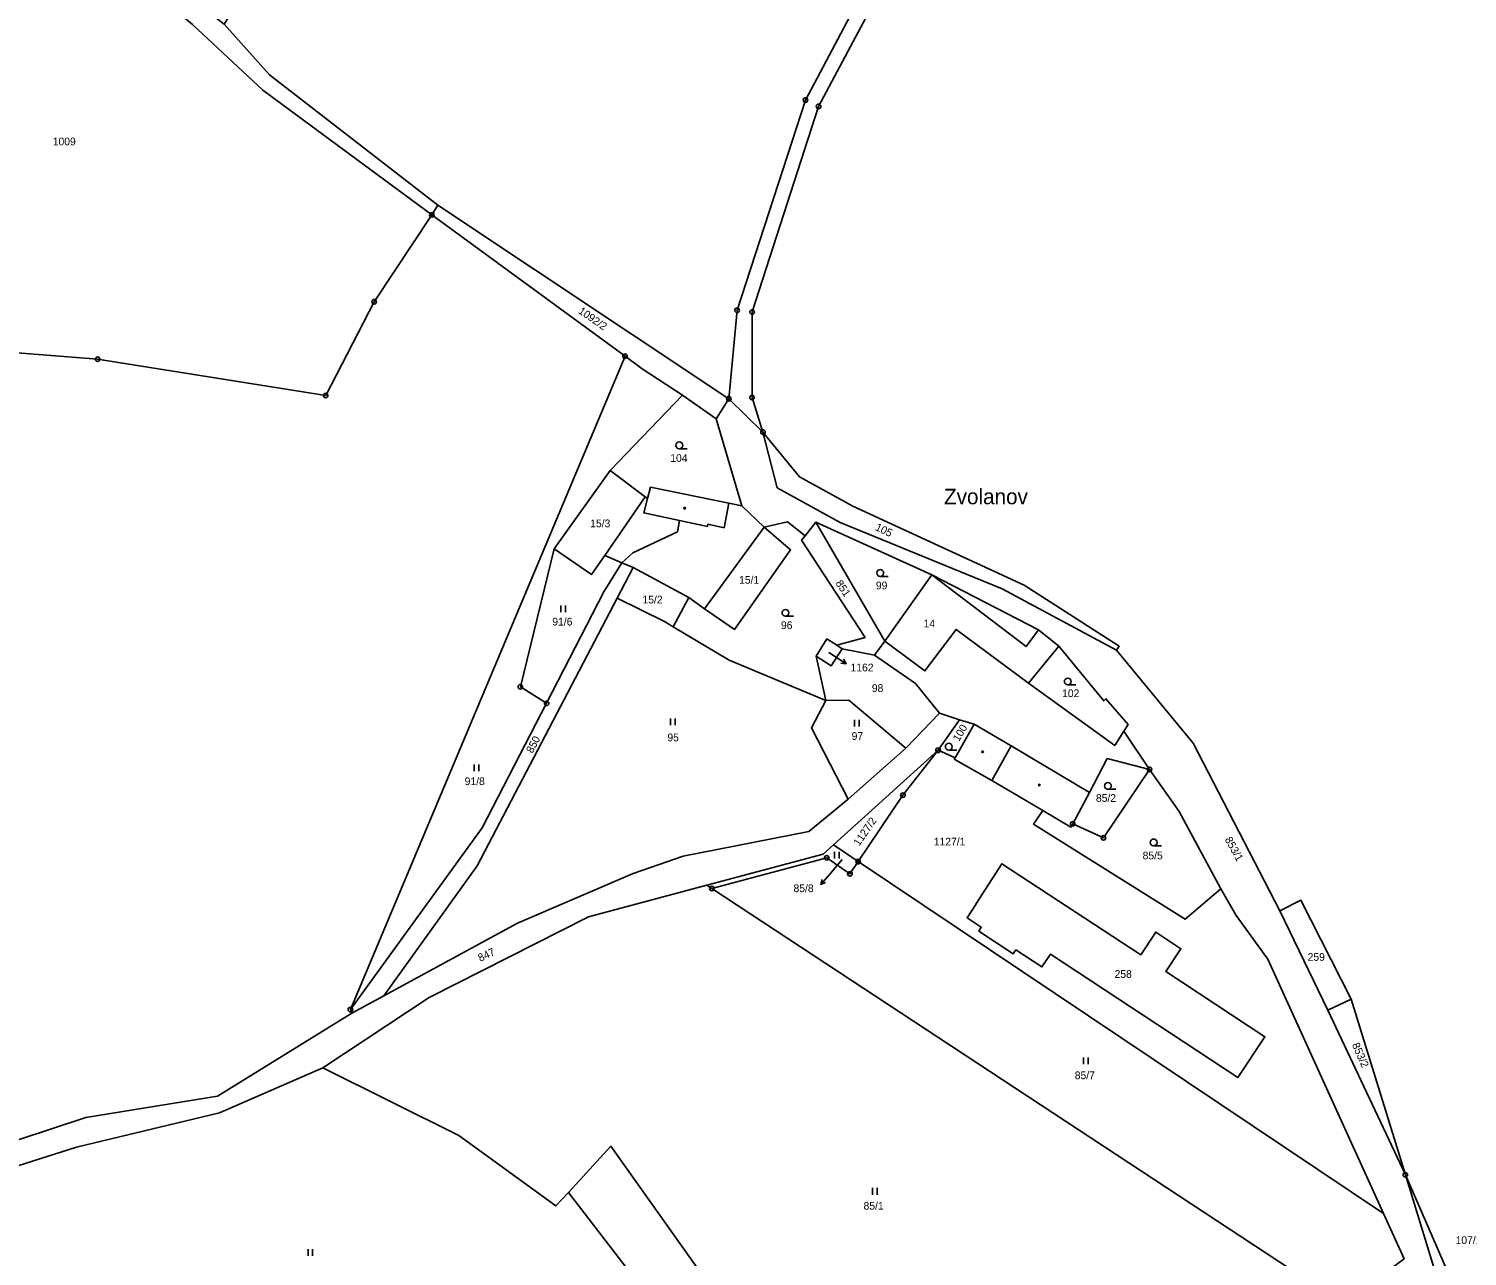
# Model space of a CAD drawing. Extents: x -654083 to -650132, y -1099819 to -1096699.
# Drawn here: x -652774.8 to -652458.4, y -1097734.5 to -1097464.5 of the extents above; entities that cross this region are included whole.
import ezdxf

# ---------------------------------------------------------------- set-up
doc = ezdxf.new("R2010")
doc.units = 0
for name, color, linetype in [('Geodetické body', 7, 'Continuous'), ('Hranice - vnitř_ kresba', 7, 'Continuous'), ('Obvody jako plochy', 7, 'Continuous'), ('Parcelní čísla', 7, 'Continuous'), ('Prvky pro prodl_ par_ č_', 7, 'Continuous'), ('Značky kultur', 7, 'Continuous'), ('Značky na budově ne v SPI', 7, 'Continuous')]:
    doc.layers.add(name, color=color, linetype=linetype)

msp = doc.modelspace()

# ---------------------------------------------------------------- linework, layer by layer
at = {"layer": 'Geodetické body'}
for centre, radius in [((-652603.96, -1097480.16), 0.5), ((-652603.96, -1097480.16), 0.001), ((-652601.09, -1097481.55), 0.5), ((-652601.09, -1097481.55), 0.001), ((-652686.17, -1097505.42), 0.5), ((-652686.17, -1097505.42), 0.001), ((-652698.86, -1097524.53), 0.5), ((-652698.86, -1097524.53), 0.001), ((-652619.02, -1097526.4), 0.5), ((-652619.02, -1097526.4), 0.001), ((-652615.72, -1097526.78), 0.5), ((-652615.72, -1097526.78), 0.001), ((-652759.69, -1097537.16), 0.5), ((-652759.69, -1097537.16), 0.001), ((-652643.67, -1097536.5), 0.5), ((-652643.67, -1097536.5), 0.001), ((-652709.52, -1097545.14), 0.5), ((-652709.52, -1097545.14), 0.001), ((-652620.84, -1097545.87), 0.5), ((-652620.84, -1097545.87), 0.001), ((-652615.73, -1097545.59), 0.5), ((-652615.73, -1097545.59), 0.001), ((-652613.33, -1097553.2), 0.5), ((-652613.33, -1097553.2), 0.001), ((-652666.7, -1097609.23), 0.5), ((-652666.7, -1097609.23), 0.001), ((-652660.92, -1097612.87), 0.5), ((-652660.92, -1097612.87), 0.001), ((-652574.81, -1097623.21), 0.5), ((-652574.81, -1097623.21), 0.001), ((-652528.29, -1097627.42), 0.5), ((-652528.29, -1097627.42), 0.001), ((-652582.54, -1097633.1), 0.5), ((-652582.54, -1097633.1), 0.001), ((-652545.19, -1097639.41), 0.5), ((-652545.19, -1097639.41), 0.001), ((-652538.42, -1097642.49), 0.5), ((-652538.42, -1097642.49), 0.001), ((-652599.31, -1097646.89), 0.5), ((-652599.31, -1097646.89), 0.001), ((-652592.38, -1097647.7), 0.5), ((-652592.38, -1097647.7), 0.001), ((-652594.2, -1097650.41), 0.5), ((-652594.2, -1097650.41), 0.001), ((-652624.58, -1097653.61), 0.5), ((-652624.58, -1097653.61), 0.001), ((-652704.08, -1097680.26), 0.5), ((-652704.08, -1097680.26), 0.001), ((-652472.02, -1097716.63), 0.5), ((-652472.02, -1097716.63), 0.001)]:
    msp.add_circle(centre, radius, dxfattribs=at)
at = {"layer": 'Hranice - vnitř_ kresba'}
for p, q in [((-652648.15, -1097580.34), (-652639.21, -1097567.47)), ((-652621.86, -1097574.29), (-652620.81, -1097568.84)), ((-652631.67, -1097572.69), (-652625.56, -1097573.99)), ((-652613.06, -1097574.09), (-652626.18, -1097592.09)), ((-652625.56, -1097573.99), (-652625.43, -1097573.47)), ((-652625.43, -1097573.47), (-652621.86, -1097574.29)), ((-652576.2, -1097584.58), (-652555.46, -1097600.41)), ((-652577.7, -1097605.76), (-652570.84, -1097596.62)), ((-652570.84, -1097596.62), (-652554.93, -1097608.48)), ((-652555.46, -1097600.41), (-652552.71, -1097596.71)), ((-652586.53, -1097599.19), (-652577.7, -1097605.76)), ((-652566.85, -1097617.5), (-652558.73, -1097622.26)), ((-652563.01, -1097629.83), (-652558.73, -1097622.26)), ((-652558.73, -1097622.26), (-652541.53, -1097632.49))]:
    msp.add_line(p, q, dxfattribs=at)
at = {"layer": 'Obvody jako plochy'}
for points in [[(-652779.91, -1097157), (-652715.26, -1097196.97), (-652590.14, -1097278.3), (-652526.21, -1097316.66), (-652529.9, -1097324.59), (-652535.99, -1097351.44), (-652570.27, -1097416.48), (-652603.96, -1097480.16), (-652619.02, -1097526.4), (-652620.84, -1097545.87), (-652684.88, -1097503.25), (-652721.85, -1097474.57), (-652731.88, -1097463.43), (-652716.7, -1097438.78), (-652701.73, -1097407.42), (-652776.86, -1097357.53)], [(-652567.26, -1097417.96), (-652601.09, -1097481.55), (-652615.72, -1097526.78), (-652615.73, -1097545.59), (-652613.33, -1097553.2), (-652605.29, -1097563.04), (-652593.55, -1097569.53), (-652555.88, -1097586.88), (-652534.94, -1097600.33), (-652535.54, -1097601.21), (-652518.69, -1097621.63), (-652499.64, -1097658.57), (-652495, -1097656.2), (-652483.9, -1097677.97), (-652472.02, -1097716.63), (-652460.01, -1097744.14)], [(-652464.12, -1097742.29), (-652472.02, -1097716.63), (-652489.06, -1097680.38), (-652499.64, -1097658.57), (-652518.69, -1097621.63), (-652535.54, -1097601.21), (-652560.69, -1097587.71), (-652596.38, -1097573.13), (-652610.2, -1097565.45), (-652613.33, -1097553.2), (-652620.84, -1097545.87), (-652623.62, -1097550.31), (-652617.97, -1097569.42), (-652613.06, -1097574.09), (-652607.91, -1097572.98), (-652604.08, -1097576.01), (-652601.71, -1097573.04), (-652576.2, -1097584.58), (-652552.71, -1097596.71), (-652548.21, -1097600.29), (-652538.38, -1097612.35), (-652537.87, -1097611.86), (-652533.01, -1097617.56), (-652533.92, -1097618.97), (-652528.29, -1097627.42), (-652521.77, -1097636.67), (-652512.63, -1097653.66), (-652509.22, -1097659.56), (-652502.27, -1097669.17), (-652476.86, -1097725.12), (-652472.31, -1097735.13)], [(-652798.05, -1097721.22), (-652764.33, -1097710.56), (-652732.87, -1097703), (-652710.18, -1097693.08), (-652686.75, -1097677.62), (-652651.73, -1097659.87), (-652625.66, -1097652.9), (-652600.05, -1097646.06), (-652597.83, -1097644.05), (-652574.81, -1097623.21), (-652570.13, -1097616.52), (-652574.49, -1097615.05), (-652581.93, -1097622.77), (-652594.62, -1097633.97), (-652603.25, -1097641.1), (-652630.86, -1097646.51), (-652641.91, -1097650.32), (-652667.32, -1097661.23), (-652696.72, -1097677.2), (-652703.74, -1097681.04), (-652733.31, -1097699.33), (-652762.26, -1097704.03), (-652800.56, -1097716.65)]]:
    msp.add_lwpolyline(points, dxfattribs=at)
for points in [[(-652540.18, -1097370.31), (-652533.47, -1097353.74), (-652526.82, -1097327.91), (-652529.9, -1097324.59), (-652535.99, -1097351.44), (-652570.27, -1097416.48), (-652603.96, -1097480.16), (-652619.02, -1097526.4), (-652620.84, -1097545.87), (-652613.33, -1097553.2), (-652615.73, -1097545.59), (-652615.72, -1097526.78), (-652601.09, -1097481.55), (-652567.26, -1097417.96)], [(-652738.79, -1097463.51), (-652723.31, -1097477.96), (-652686.17, -1097505.42), (-652684.88, -1097503.25), (-652721.85, -1097474.57), (-652731.88, -1097463.43), (-652810.78, -1097402.98), (-652813.96, -1097400.29), (-652829.11, -1097384.9), (-652839.28, -1097373.4), (-652849.11, -1097371.52), (-652872.13, -1097365.2), (-652876.66, -1097364.67), (-652880.8, -1097361.29), (-652880.84, -1097364.37), (-652882.96, -1097367.55), (-652864.52, -1097371.39), (-652843.44, -1097375.42), (-652819.55, -1097400.48), (-652800.97, -1097415.17), (-652754.06, -1097450.74)], [(-652850.71, -1097530.01), (-652827.34, -1097478.42), (-652810.09, -1097436.14), (-652800.97, -1097415.17), (-652754.06, -1097450.74), (-652738.79, -1097463.51), (-652723.31, -1097477.96), (-652686.17, -1097505.42), (-652698.86, -1097524.53), (-652709.52, -1097545.14), (-652759.69, -1097537.16)], [(-652704.08, -1097680.26), (-652703.74, -1097681.04), (-652733.31, -1097699.33), (-652762.26, -1097704.03), (-652800.56, -1097716.65), (-652815.65, -1097731.6), (-652828.56, -1097725.87), (-652992.49, -1097649.57), (-652989.71, -1097646.97), (-652979.65, -1097631.11), (-652958.9, -1097581.47), (-652940.9, -1097529.1), (-652931.25, -1097506.84), (-652921.26, -1097492.09), (-652899.7, -1097506.2), (-652857.74, -1097539.18), (-652850.71, -1097530.01), (-652759.69, -1097537.16), (-652709.52, -1097545.14), (-652698.86, -1097524.53), (-652686.17, -1097505.42), (-652643.67, -1097536.5)], [(-652620.84, -1097545.87), (-652623.62, -1097550.31), (-652631.03, -1097545.07), (-652639.88, -1097539.27), (-652643.67, -1097536.5), (-652686.17, -1097505.42), (-652684.88, -1097503.25)], [(-652660.92, -1097612.87), (-652675.13, -1097640.3), (-652704.08, -1097680.26), (-652643.67, -1097536.5), (-652639.88, -1097539.27), (-652631.03, -1097545.07), (-652646.94, -1097561.68), (-652659.25, -1097578.86), (-652666.7, -1097609.23)], [(-652623.62, -1097550.31), (-652617.97, -1097569.42), (-652620.81, -1097568.84), (-652638.07, -1097565.33), (-652638.73, -1097567.83), (-652639.21, -1097567.47), (-652646.94, -1097561.68), (-652631.03, -1097545.07)], [(-652555.88, -1097586.88), (-652534.94, -1097600.33), (-652535.54, -1097601.21), (-652560.69, -1097587.71), (-652596.38, -1097573.13), (-652610.2, -1097565.45), (-652613.33, -1097553.2), (-652605.29, -1097563.04), (-652593.55, -1097569.53)], [(-652646.94, -1097561.68), (-652639.21, -1097567.47), (-652638.73, -1097567.83), (-652639.57, -1097571), (-652631.67, -1097572.69), (-652632.14, -1097575.17), (-652641.98, -1097579.75), (-652644.37, -1097581.95), (-652648.15, -1097580.34), (-652651.08, -1097584.55), (-652659.25, -1097578.86)], [(-652648.15, -1097580.34), (-652639.21, -1097567.47), (-652646.94, -1097561.68), (-652659.25, -1097578.86), (-652651.08, -1097584.55)], [(-652607.24, -1097579.12), (-652619.59, -1097596.65), (-652626.18, -1097592.09), (-652629.64, -1097589.6), (-652641.87, -1097583.01), (-652644.37, -1097581.95), (-652641.98, -1097579.75), (-652632.14, -1097575.17), (-652631.67, -1097572.69), (-652639.57, -1097571), (-652638.73, -1097567.83), (-652638.07, -1097565.33), (-652620.81, -1097568.84), (-652617.97, -1097569.42), (-652613.06, -1097574.09)], [(-652599.25, -1097598.72), (-652601.64, -1097602.49), (-652599.49, -1097612.24), (-652620.77, -1097603.4), (-652633.07, -1097596.05), (-652629.64, -1097589.6), (-652626.18, -1097592.09), (-652619.59, -1097596.65), (-652607.24, -1097579.12), (-652613.06, -1097574.09), (-652607.91, -1097572.98), (-652604.08, -1097576.01), (-652604.84, -1097576.95), (-652590.88, -1097598.37), (-652597.08, -1097600.09)], [(-652607.24, -1097579.12), (-652619.59, -1097596.65), (-652626.18, -1097592.09), (-652613.06, -1097574.09)], [(-652601.71, -1097573.04), (-652586.53, -1097599.19), (-652588.78, -1097602.31), (-652595.87, -1097600.86), (-652597.08, -1097600.09), (-652590.88, -1097598.37), (-652604.84, -1097576.95), (-652604.08, -1097576.01)], [(-652601.71, -1097573.04), (-652576.2, -1097584.58), (-652586.53, -1097599.19)], [(-652644.37, -1097581.95), (-652648.15, -1097580.34), (-652651.08, -1097584.55), (-652659.25, -1097578.86), (-652666.7, -1097609.23), (-652660.92, -1097612.87), (-652648.31, -1097588.32)], [(-652648.31, -1097588.32), (-652660.92, -1097612.87), (-652675.13, -1097640.3), (-652704.08, -1097680.26), (-652703.74, -1097681.04), (-652696.72, -1097677.2), (-652676.18, -1097648.6), (-652645.43, -1097589.75), (-652641.87, -1097583.01), (-652644.37, -1097581.95)], [(-652629.64, -1097589.6), (-652633.07, -1097596.05), (-652634.98, -1097594.91), (-652645.43, -1097589.75), (-652641.87, -1097583.01)], [(-652645.43, -1097589.75), (-652641.87, -1097583.01), (-652629.64, -1097589.6), (-652633.07, -1097596.05), (-652634.98, -1097594.91)], [(-652552.71, -1097596.71), (-652548.21, -1097600.29), (-652554.93, -1097608.48), (-652535.96, -1097622.13), (-652533.92, -1097618.97), (-652528.29, -1097627.42), (-652537.6, -1097625.03), (-652541.53, -1097632.49), (-652545.19, -1097639.41), (-652545.57, -1097640.1), (-652551.79, -1097636.44), (-652563.01, -1097629.83), (-652571.26, -1097625.16), (-652571.07, -1097624.84), (-652566.85, -1097617.5), (-652570.13, -1097616.52), (-652574.49, -1097615.05), (-652579.78, -1097608.52), (-652588.78, -1097602.31), (-652586.53, -1097599.19), (-652576.2, -1097584.58)], [(-652548.21, -1097600.29), (-652554.93, -1097608.48), (-652570.84, -1097596.62), (-652577.7, -1097605.76), (-652586.53, -1097599.19), (-652576.2, -1097584.58), (-652555.46, -1097600.41), (-652552.71, -1097596.71)], [(-652599.49, -1097612.24), (-652620.77, -1097603.4), (-652633.07, -1097596.05), (-652634.98, -1097594.91), (-652645.43, -1097589.75), (-652676.18, -1097648.6), (-652696.72, -1097677.2), (-652667.32, -1097661.23), (-652641.91, -1097650.32), (-652630.86, -1097646.51), (-652603.25, -1097641.1), (-652594.62, -1097633.97), (-652602.68, -1097618.27)], [(-652595.87, -1097600.86), (-652597.08, -1097600.09), (-652599.25, -1097598.72), (-652601.64, -1097602.49), (-652598.3, -1097604.6)], [(-652533.01, -1097617.56), (-652537.87, -1097611.86), (-652538.38, -1097612.35), (-652548.21, -1097600.29), (-652554.93, -1097608.48), (-652535.96, -1097622.13), (-652533.92, -1097618.97)], [(-652579.78, -1097608.52), (-652574.49, -1097615.05), (-652581.93, -1097622.77), (-652594.47, -1097612.18), (-652599.49, -1097612.24), (-652601.64, -1097602.49), (-652598.3, -1097604.6), (-652595.87, -1097600.86), (-652588.78, -1097602.31)], [(-652594.47, -1097612.18), (-652599.49, -1097612.24), (-652602.68, -1097618.27), (-652594.62, -1097633.97), (-652581.93, -1097622.77)], [(-652570.13, -1097616.52), (-652566.85, -1097617.5), (-652571.07, -1097624.84), (-652574.81, -1097623.21)], [(-652582.54, -1097633.1), (-652592.38, -1097647.7), (-652597.83, -1097644.05), (-652574.81, -1097623.21)], [(-652512.63, -1097653.66), (-652509.22, -1097659.56), (-652502.27, -1097669.17), (-652476.86, -1097725.12), (-652592.38, -1097647.7), (-652582.54, -1097633.1), (-652574.81, -1097623.21), (-652571.07, -1097624.84), (-652571.26, -1097625.16), (-652563.01, -1097629.83), (-652551.79, -1097636.44), (-652553.8, -1097639.5), (-652520.42, -1097660.37)], [(-652538.42, -1097642.49), (-652528.29, -1097627.42), (-652537.6, -1097625.03), (-652541.53, -1097632.49), (-652545.19, -1097639.41)], [(-652528.29, -1097627.42), (-652521.77, -1097636.67), (-652512.63, -1097653.66), (-652520.42, -1097660.37), (-652553.8, -1097639.5), (-652551.79, -1097636.44), (-652545.57, -1097640.1), (-652545.19, -1097639.41), (-652538.42, -1097642.49)], [(-652594.2, -1097650.41), (-652599.31, -1097646.89), (-652624.58, -1097653.61), (-652625.66, -1097652.9), (-652600.05, -1097646.06), (-652597.83, -1097644.05), (-652592.38, -1097647.7)], [(-652476.86, -1097725.12), (-652472.31, -1097735.13), (-652473.35, -1097735.9), (-652485.69, -1097745.02), (-652624.58, -1097653.61), (-652599.31, -1097646.89), (-652594.2, -1097650.41), (-652592.38, -1097647.7)], [(-652530.2, -1097668.19), (-652526.92, -1097663.21), (-652521.37, -1097666.87), (-652524.68, -1097671.89), (-652502.92, -1097686.24), (-652508.84, -1097695.24), (-652550.09, -1097668.1), (-652551.98, -1097670.88), (-652557.72, -1097667.14), (-652558.27, -1097667.98), (-652565.86, -1097662.98), (-652565.3, -1097662.12), (-652568.41, -1097660.07), (-652566.47, -1097657.13), (-652566.53, -1097657.09), (-652560.76, -1097648.18)], [(-652550.09, -1097668.1), (-652551.98, -1097670.88), (-652557.72, -1097667.14), (-652558.27, -1097667.98), (-652565.86, -1097662.98), (-652565.3, -1097662.12), (-652568.41, -1097660.07), (-652566.47, -1097657.13), (-652566.53, -1097657.09), (-652560.76, -1097648.18), (-652530.2, -1097668.19), (-652526.92, -1097663.21), (-652521.37, -1097666.87), (-652524.68, -1097671.89), (-652502.92, -1097686.24), (-652508.84, -1097695.24)], [(-652565.86, -1097662.98), (-652565.3, -1097662.12), (-652568.41, -1097660.07), (-652566.47, -1097657.13), (-652566.53, -1097657.09), (-652560.76, -1097648.18), (-652530.2, -1097668.19), (-652526.92, -1097663.21), (-652521.37, -1097666.87), (-652524.68, -1097671.89), (-652502.92, -1097686.24), (-652508.84, -1097695.24), (-652550.09, -1097668.1), (-652551.98, -1097670.88), (-652557.72, -1097667.14), (-652558.27, -1097667.98)], [(-652544.27, -1097792.84), (-652498.55, -1097834.17), (-652500.72, -1097835.3), (-652505.04, -1097839.66), (-652506.28, -1097838.58), (-652540.54, -1097816.45), (-652565.83, -1097800.14), (-652615.96, -1097753.79), (-652646.78, -1097710.34), (-652656.09, -1097720.49), (-652658.92, -1097723.47), (-652680.26, -1097707.97), (-652710.18, -1097693.08), (-652686.75, -1097677.62), (-652651.73, -1097659.87), (-652625.66, -1097652.9), (-652624.58, -1097653.61), (-652485.69, -1097745.02)], [(-652483.9, -1097677.97), (-652489.06, -1097680.38), (-652499.64, -1097658.57), (-652495, -1097656.2)], [(-652495, -1097656.2), (-652499.64, -1097658.57), (-652489.06, -1097680.38), (-652483.9, -1097677.97)], [(-652472.02, -1097716.63), (-652483.9, -1097677.97), (-652489.06, -1097680.38)], [(-652658.92, -1097723.47), (-652656.09, -1097720.49), (-652641.41, -1097739.54), (-652635.71, -1097759.4), (-652641.84, -1097752.88), (-652676.84, -1097793.83), (-652695.77, -1097785.5), (-652811.07, -1097733.73), (-652798.05, -1097721.22), (-652764.33, -1097710.56), (-652732.87, -1097703), (-652710.18, -1097693.08), (-652680.26, -1097707.97)], [(-652565.83, -1097800.14), (-652573.01, -1097818.76), (-652635.71, -1097759.4), (-652641.41, -1097739.54), (-652656.09, -1097720.49), (-652646.78, -1097710.34), (-652615.96, -1097753.79)], [(-652460.01, -1097744.14), (-652464.12, -1097742.29), (-652472.02, -1097716.63)]]:
    msp.add_lwpolyline(points, close=True, dxfattribs=at)
at = {"layer": 'Prvky pro prodl_ par_ č_'}
for p, q in [((-652598.83, -1097601.7), (-652597.57, -1097602.52)), ((-652597.57, -1097602.52), (-652595.06, -1097604.16)), ((-652595.92, -1097647.27), (-652598.65, -1097650.44)), ((-652598.65, -1097650.44), (-652600.6, -1097652.72))]:
    msp.add_line(p, q, dxfattribs=at)
for points in [[(-652595.62, -1097603.19), (-652595.06, -1097604.16), (-652596.17, -1097604.03)], [(-652599.57, -1097652.28), (-652600.6, -1097652.72), (-652600.33, -1097651.63)]]:
    msp.add_lwpolyline(points, dxfattribs=at)
at = {"layer": 'Značky kultur'}
for p, q in [((-652629.99, -1097556.87), (-652631.74, -1097556.87)), ((-652585.78, -1097584.95), (-652587.53, -1097584.95)), ((-652657.76, -1097591.35), (-652657.76, -1097592.85)), ((-652656.73, -1097592.85), (-652656.73, -1097591.35)), ((-652606.63, -1097593.72), (-652608.38, -1097593.72)), ((-652544.52, -1097608.83), (-652546.27, -1097608.83)), ((-652633.66, -1097616.19), (-652633.66, -1097617.69)), ((-652632.64, -1097617.69), (-652632.64, -1097616.19)), ((-652593.16, -1097616.49), (-652593.16, -1097617.99)), ((-652592.14, -1097617.99), (-652592.14, -1097616.49)), ((-652570.7, -1097623.18), (-652572.45, -1097623.18)), ((-652676.84, -1097626.34), (-652676.84, -1097627.84)), ((-652675.82, -1097627.84), (-652675.82, -1097626.34)), ((-652535.7, -1097631.8), (-652537.45, -1097631.8)), ((-652525.64, -1097644.24), (-652527.39, -1097644.24)), ((-652597.61, -1097645.53), (-652597.61, -1097647.03)), ((-652596.58, -1097647.03), (-652596.58, -1097645.53)), ((-652542.79, -1097690.77), (-652542.79, -1097692.27)), ((-652541.77, -1097692.27), (-652541.77, -1097690.77)), ((-652589.22, -1097719.51), (-652589.22, -1097721.01)), ((-652588.2, -1097721.01), (-652588.2, -1097719.51)), ((-652713.41, -1097732.95), (-652713.41, -1097734.45)), ((-652712.39, -1097734.45), (-652712.39, -1097732.95))]:
    msp.add_line(p, q, dxfattribs=at)
for centre in [(-652631.74, -1097556.12), (-652587.53, -1097584.2), (-652608.38, -1097592.97), (-652546.27, -1097608.08), (-652572.45, -1097622.43), (-652537.45, -1097631.05), (-652527.39, -1097643.49)]:
    msp.add_circle(centre, 0.75, dxfattribs=at)
at = {"layer": 'Značky na budově ne v SPI'}
for centre in [(-652630.56, -1097569.94), (-652565.02, -1097623.55), (-652552.52, -1097630.87)]:
    msp.add_circle(centre, 0.175, dxfattribs=at)

# ---------------------------------------------------------------- texts
at = {"layer": 'Obvody jako plochy'}
msp.add_text('Zvolanov', height=3.4, dxfattribs=at).set_placement((-652573.5, -1097569.09))
at = {"layer": 'Parcelní čísla'}
for s, height, p in [('1009', 1.7, (-652769.56, -1097490.12)), ('104', 1.7, (-652633.72, -1097559.77)), ('15/3', 1.7, (-652651.33, -1097574.14)), ('15/1', 1.7, (-652618.58, -1097586.57)), ('99', 1.7, (-652588.49, -1097587.81)), ('15/2', 1.7, (-652639.83, -1097590.9)), ('91/6', 1.7, (-652659.67, -1097595.76)), ('96', 1.7, (-652609.37, -1097596.55)), ('14', 1.7, (-652577.99, -1097596.17)), ('1162', 0.1, (-652598.93, -1097601.7)), ('98', 1.7, (-652589.38, -1097610.38)), ('102', 1.7, (-652547.53, -1097611.52)), ('95', 1.7, (-652634.35, -1097621.23)), ('97', 1.7, (-652593.82, -1097620.92)), ('91/8', 1.7, (-652678.95, -1097630.88)), ('85/2', 1.7, (-652540.08, -1097634.56)), ('1127/1', 1.7, (-652575.75, -1097644.16)), ('85/8', 0.1, (-652596.07, -1097647.27)), ('85/5', 1.7, (-652529.81, -1097647.21)), ('259', 1.7, (-652493.51, -1097669.53)), ('258', 1.7, (-652535.98, -1097673.28)), ('85/7', 1.7, (-652544.74, -1097695.58)), ('85/1', 1.7, (-652591.2, -1097724.28))]:
    msp.add_text(s, height=height, dxfattribs=at).set_placement(p)
for s, rotation, p in [('1092/2', 325.098, (-652654.09, -1097526.92)), ('105', 334.494, (-652588.78, -1097574.7)), ('851', 303.876, (-652597.45, -1097586.47)), ('100', 59.067, (-652570.23, -1097621.43)), ('850', 62.199, (-652664.02, -1097624)), ('1127/2', 55.701, (-652592.16, -1097644.43)), ('853/1', 298.908, (-652511.81, -1097642.82)), ('847', 25.191, (-652675.53, -1097669.76)), ('853/2', 293.787, (-652483.81, -1097688))]:
    msp.add_text(s, height=1.7, rotation=rotation, dxfattribs=at).set_placement(p)
at = {"layer": 'Prvky pro prodl_ par_ č_'}
for s, p in [('1162', (-652594.06, -1097605.86)), ('85/8', (-652606.61, -1097654.42)), ('107/10', (-652460.97, -1097731.84))]:
    msp.add_text(s, height=1.7, dxfattribs=at).set_placement(p)

doc.saveas('drawing.dxf')
